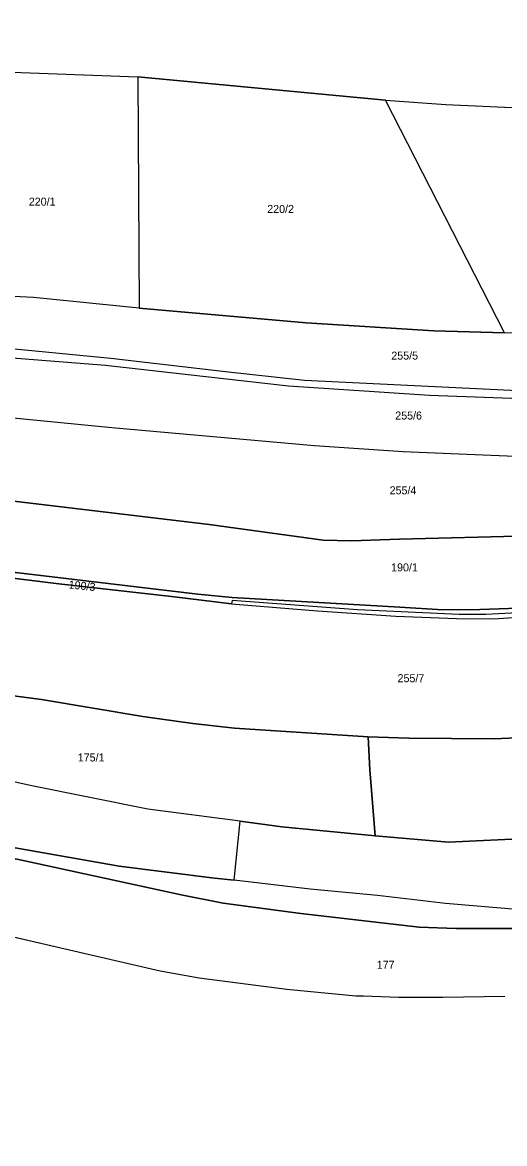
# Model space of a CAD drawing. Extents: x -629983 to -626385, y -1072828 to -1067897.
# Drawn here: x -628471.3 to -628290.3, y -1071600.2 to -1071180 of the extents above; entities that cross this region are included whole.
import ezdxf

# ---------------------------------------------------------------- set-up
doc = ezdxf.new("R2010")
doc.units = 0
for name, color, linetype in [('Parcela nároku', 7, 'Continuous'), ('Parcelní číslo', 7, 'Continuous'), ('Plocha PÚ', 7, 'Continuous'), ('Šetřený obvod', 7, 'Continuous')]:
    doc.layers.add(name, color=color, linetype=linetype)

msp = doc.modelspace()

# ---------------------------------------------------------------- linework, layer by layer
at = {"layer": 'Parcela nároku'}
for points in [[(-628268.25, -1071136.94), (-628291.93, -1071135.53), (-628338.35, -1071130.97), (-628459.92, -1071116.05), (-628500.56, -1071112.2), (-628502.21, -1071114.01), (-628507.6, -1071121.45), (-628532.34, -1071151.07), (-628548.36, -1071170.68), (-628564.48, -1071189.84), (-628502.34, -1071196.75), (-628482.19, -1071198.25), (-628480.08, -1071198.41), (-628478.48, -1071198.53), (-628427.9, -1071200.4), (-628334.96, -1071209.11), (-628312.3, -1071210.8), (-628248.73, -1071213.64)], [(-628808.2, -1071481.19), (-628760.79, -1071438.02), (-628697, -1071379.49), (-628648.46, -1071337.03), (-628601.61, -1071298.55), (-628588.07, -1071293.27), (-628528.38, -1071298.52), (-628524.42, -1071298.51), (-628482.04, -1071301.6), (-628438.06, -1071305.8), (-628395.02, -1071310.8), (-628365.42, -1071314.12), (-628275.13, -1071318.47)], [(-628273.93, -1071321.45), (-628318.54, -1071319.86), (-628371.43, -1071316.29), (-628440.08, -1071308.56), (-628526.04, -1071301.81), (-628530.62, -1071301.48), (-628587.07, -1071297.35), (-628600.55, -1071302.08), (-628651.84, -1071343.72), (-628693.44, -1071380.48), (-628804.41, -1071481.81)], [(-628274.23, -1071399.23), (-628303.29, -1071400.24), (-628315.54, -1071400.06), (-628329.58, -1071399.22), (-628392.55, -1071395.56), (-628405.46, -1071394.36), (-628474.86, -1071386.07), (-628541.01, -1071378.58), (-628538.52, -1071351.85), (-628401.12, -1071368.15), (-628358.35, -1071374.06), (-628347.75, -1071374.26), (-628329.76, -1071373.7), (-628280.79, -1071372.47)], [(-628287.84, -1071401.42), (-628297.35, -1071401.88), (-628307.32, -1071401.88), (-628321.05, -1071401.36), (-628345.5, -1071400.17), (-628392.57, -1071396.64), (-628392.8, -1071397.95), (-628415.25, -1071395.22), (-628457.59, -1071390.49), (-628541.17, -1071380.21), (-628544.72, -1071379.87), (-628570.71, -1071376.62), (-628570.47, -1071374.45), (-628544.42, -1071378.28), (-628541.01, -1071378.58), (-628474.86, -1071386.07), (-628405.46, -1071394.36), (-628392.55, -1071395.56), (-628329.58, -1071399.22), (-628315.54, -1071400.06), (-628303.29, -1071400.24), (-628274.23, -1071399.23)], [(-628274.57, -1071447.7), (-628294.28, -1071448.53), (-628326.21, -1071448.26), (-628341.49, -1071447.8), (-628391.61, -1071444.51), (-628407.33, -1071442.73), (-628426, -1071440.17), (-628464.1, -1071433.74), (-628506.16, -1071428.31), (-628552.16, -1071422.26), (-628544.31, -1071400.02), (-628541.17, -1071380.21), (-628457.59, -1071390.49), (-628415.25, -1071395.22), (-628392.8, -1071397.95), (-628360.53, -1071400.59), (-628331.13, -1071402.58), (-628308.34, -1071403.38), (-628294.44, -1071403.56), (-628268.12, -1071401.86)], [(-628284.37, -1071512.65), (-628312.52, -1071510.23), (-628338.05, -1071507.24), (-628363.21, -1071504.86), (-628391.85, -1071501.56), (-628399.19, -1071500.71), (-628434.88, -1071496.23), (-628473.93, -1071489.43), (-628490.89, -1071485.98), (-628515.31, -1071479.08), (-628529.67, -1071476.01), (-628579.15, -1071469.02), (-628597.27, -1071469.13), (-628616.57, -1071487.55), (-628642.81, -1071512.25), (-628668.5, -1071534.73), (-628691.58, -1071545.39), (-628744.05, -1071599.5), (-628762.74, -1071614.04)], [(-628284.37, -1071512.65), (-628312.52, -1071510.23), (-628338.05, -1071507.24), (-628363.21, -1071504.86), (-628391.85, -1071501.56), (-628389.52, -1071479.4), (-628373.91, -1071481.53), (-628338.84, -1071484.87), (-628311.42, -1071487.21), (-628277.06, -1071485.64)], [(-628285.56, -1071519.59), (-628308.46, -1071519.67), (-628322.34, -1071519.08), (-628366.71, -1071514.01), (-628395.94, -1071510.13), (-628411.65, -1071506.99), (-628473.85, -1071493.45), (-628499.5, -1071516.96), (-628455.23, -1071527.2), (-628419.52, -1071535.52), (-628404.93, -1071538.15), (-628372.02, -1071542.3), (-628346.18, -1071544.83), (-628343.24, -1071544.92), (-628330.14, -1071545.31), (-628313.5, -1071545.35), (-628290.22, -1071544.96)], [(-628473.85, -1071493.45), (-628411.65, -1071506.99), (-628395.94, -1071510.13), (-628366.71, -1071514.01), (-628322.34, -1071519.08), (-628308.46, -1071519.67), (-628285.56, -1071519.59)]]:
    msp.add_lwpolyline(points, dxfattribs=at)
for points in [[(-628478.48, -1071198.53), (-628427.9, -1071200.4), (-628427.39, -1071287.11), (-628467.03, -1071283.14), (-628517.75, -1071280.56)], [(-628290.4, -1071296.4), (-628334.96, -1071209.11), (-628427.9, -1071200.4), (-628427.39, -1071287.11), (-628364.74, -1071292.65), (-628316.82, -1071295.58)], [(-628248.73, -1071213.64), (-628242.24, -1071297.42), (-628290.4, -1071296.4), (-628334.96, -1071209.11), (-628312.3, -1071210.8)], [(-628208.79, -1071296.49), (-628242.24, -1071297.42), (-628290.4, -1071296.4), (-628316.82, -1071295.58), (-628364.74, -1071292.65), (-628427.39, -1071287.11), (-628467.03, -1071283.14), (-628517.75, -1071280.56), (-628524.42, -1071298.51), (-628482.04, -1071301.6), (-628438.06, -1071305.8), (-628395.02, -1071310.8), (-628365.42, -1071314.12), (-628275.13, -1071318.47), (-628253.61, -1071317.5), (-628207.37, -1071314.88), (-628142.44, -1071305.66), (-628108.62, -1071298.61), (-628073.11, -1071285.89), (-628061.01, -1071263.12), (-628082.05, -1071270.57), (-628126.01, -1071284.19), (-628138.45, -1071287.1), (-628171.64, -1071292.78)], [(-628107.14, -1071301.3), (-628131.89, -1071306.72), (-628168.32, -1071312.98), (-628214.06, -1071318.59), (-628244.37, -1071320.84), (-628273.93, -1071321.45), (-628318.54, -1071319.86), (-628371.43, -1071316.29), (-628440.08, -1071308.56), (-628526.04, -1071301.81), (-628534.77, -1071322.4), (-628437.67, -1071331.83), (-628361.69, -1071338.57), (-628328.43, -1071340.82), (-628286.36, -1071342.53), (-628238.25, -1071341.91), (-628212.54, -1071339.87), (-628176.11, -1071334.77), (-628141.31, -1071328.32), (-628126.29, -1071324.47), (-628086.27, -1071311.66), (-628085.77, -1071310.46), (-628083.67, -1071305.78), (-628075.46, -1071290.32)], [(-628361.69, -1071338.57), (-628328.43, -1071340.82), (-628286.36, -1071342.53), (-628238.25, -1071341.91), (-628212.54, -1071339.87), (-628176.11, -1071334.77), (-628141.31, -1071328.32), (-628126.29, -1071324.47), (-628086.27, -1071311.66), (-628098.7, -1071341.18), (-628142.69, -1071353.16), (-628166.54, -1071357.54), (-628240.16, -1071369.08), (-628261.61, -1071371.41), (-628280.79, -1071372.47), (-628329.76, -1071373.7), (-628347.75, -1071374.26), (-628358.35, -1071374.06), (-628401.12, -1071368.15), (-628538.52, -1071351.85), (-628535.81, -1071326.91), (-628534.77, -1071322.4), (-628437.67, -1071331.83)], [(-628199.75, -1071393.51), (-628139.52, -1071382.42), (-628109.96, -1071376.13), (-628109.63, -1071374.64), (-628148.17, -1071382.64), (-628198.97, -1071391.68), (-628227.27, -1071395.83), (-628271.16, -1071400.56), (-628287.84, -1071401.42), (-628297.35, -1071401.88), (-628307.32, -1071401.88), (-628321.05, -1071401.36), (-628345.5, -1071400.17), (-628392.57, -1071396.64), (-628392.8, -1071397.95), (-628360.53, -1071400.59), (-628331.13, -1071402.58), (-628308.34, -1071403.38), (-628294.44, -1071403.56), (-628268.12, -1071401.86), (-628231.64, -1071397.76)], [(-628340.89, -1071460.14), (-628338.84, -1071484.87), (-628373.91, -1071481.53), (-628389.52, -1071479.4), (-628424.13, -1071474.9), (-628468.29, -1071466), (-628503.56, -1071458.21), (-628575.75, -1071445.16), (-628555.79, -1071421.73), (-628552.16, -1071422.26), (-628506.16, -1071428.31), (-628464.1, -1071433.74), (-628426, -1071440.17), (-628407.33, -1071442.73), (-628391.61, -1071444.51), (-628341.49, -1071447.8)], [(-628226.35, -1071442.54), (-628197.64, -1071438.31), (-628154.46, -1071429.81), (-628120.49, -1071422.02), (-628128.04, -1071453.5), (-628170.9, -1071462.36), (-628178.2, -1071463.53), (-628205.85, -1071470.9), (-628217.79, -1071473.7), (-628257.82, -1071481.79), (-628277.06, -1071485.64), (-628311.42, -1071487.21), (-628338.84, -1071484.87), (-628340.89, -1071460.14), (-628341.49, -1071447.8), (-628326.21, -1071448.26), (-628294.28, -1071448.53), (-628274.57, -1071447.7)], [(-628503.56, -1071458.21), (-628575.75, -1071445.16), (-628585.99, -1071457.17), (-628597.27, -1071469.13), (-628579.15, -1071469.02), (-628529.67, -1071476.01), (-628515.31, -1071479.08), (-628490.89, -1071485.98), (-628473.93, -1071489.43), (-628434.88, -1071496.23), (-628399.19, -1071500.71), (-628391.85, -1071501.56), (-628389.52, -1071479.4), (-628424.13, -1071474.9), (-628468.29, -1071466)]]:
    msp.add_lwpolyline(points, close=True, dxfattribs=at)
at = {"layer": 'Plocha PÚ'}
msp.add_lwpolyline([(-628592.01, -1071608.7), (-628569.97, -1071583.11), (-628560.83, -1071573.3), (-628549.56, -1071562.5), (-628521.02, -1071535.15), (-628501.48, -1071516.88), (-628499.5, -1071516.96), (-628455.23, -1071527.2), (-628419.52, -1071535.52), (-628404.93, -1071538.15), (-628372.02, -1071542.3), (-628346.18, -1071544.83), (-628343.24, -1071544.92), (-628330.14, -1071545.31), (-628313.5, -1071545.35), (-628290.22, -1071544.96)], dxfattribs=at)
at = {"layer": 'Šetřený obvod'}
for p, q in [((-628499.5, -1071516.96), (-628419.52, -1071535.52)), ((-628419.52, -1071535.52), (-628404.93, -1071538.15)), ((-628404.93, -1071538.15), (-628372.02, -1071542.3)), ((-628372.02, -1071542.3), (-628346.18, -1071544.83)), ((-628346.18, -1071544.83), (-628343.24, -1071544.92)), ((-628343.24, -1071544.92), (-628330.14, -1071545.31)), ((-628313.5, -1071545.35), (-628290.22, -1071544.96)), ((-628330.14, -1071545.31), (-628313.5, -1071545.35))]:
    msp.add_line(p, q, dxfattribs=at)

# ---------------------------------------------------------------- texts
at = {"layer": 'Parcelní číslo'}
for s, p in [('220/1', (-628468.85, -1071248.69)), ('220/2', (-628379.38, -1071251.43)), ('255/5', (-628332.83, -1071306.4)), ('255/6', (-628331.35, -1071328.86)), ('255/4', (-628333.46, -1071356.89)), ('190/1', (-628332.89, -1071385.77)), ('255/7', (-628330.48, -1071427.31)), ('175/1', (-628450.48, -1071457.02)), ('177', (-628338.3, -1071534.71))]:
    msp.add_text(s, height=3, dxfattribs=at).set_placement(p)
msp.add_text('190/3', height=3, rotation=354.0685, dxfattribs=at).set_placement((-628454.01, -1071392.12))

doc.saveas('drawing.dxf')
